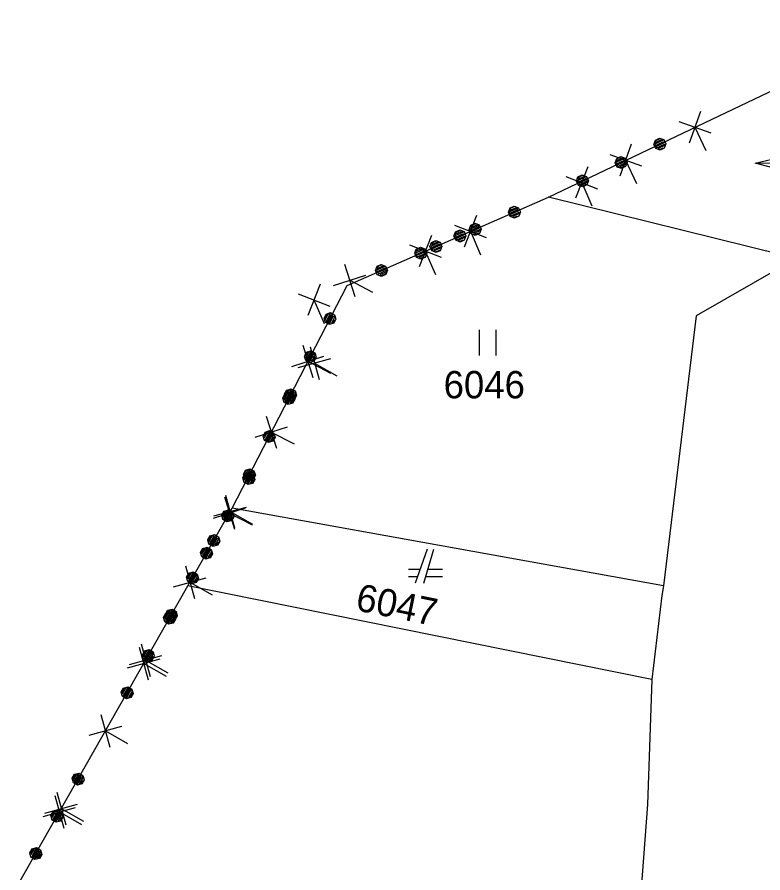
# Model space of a CAD drawing. Extents: x -266179 to -264727, y -1243225 to -1241702.
# Drawn here: x -265694.6 to -265650.9, y -1241809 to -1241758.9 of the extents above; entities that cross this region are included whole.
import ezdxf

# ---------------------------------------------------------------- set-up
doc = ezdxf.new("R2010")
doc.units = 0
for name, color, linetype in [('Vrstva 1', 7, 'Continuous'), ('Vrstva 19', 7, 'Continuous'), ('Vrstva 21', 7, 'Continuous')]:
    doc.layers.add(name, color=color, linetype=linetype)

msp = doc.modelspace()

# ---------------------------------------------------------------- linework, layer by layer
at = {"layer": 'Vrstva 1'}
for p, q in [((-265663.46, -1241769.44), (-265641.35, -1241758.91)), ((-265645.37, -1241767.516), (-265651.37, -1241767.464)), ((-265675.26, -1241774.61), (-265663.46, -1241769.44)), ((-265648.97, -1241773.03), (-265663.46, -1241769.44)), ((-265648.97, -1241773.03), (-265654.81, -1241776.39)), ((-265681.99, -1241787.64), (-265675.26, -1241774.61)), ((-265654.81, -1241776.39), (-265656.72, -1241792.19)), ((-265667.52, -1241777.21), (-265667.52, -1241778.71)), ((-265666.52, -1241778.71), (-265666.52, -1241777.21)), ((-265684.58, -1241792.19), (-265681.99, -1241787.64)), ((-265656.72, -1241792.19), (-265681.99, -1241787.64)), ((-265670.57, -1241790.04), (-265671.27, -1241792.04)), ((-265670.77, -1241792.04), (-265670.17, -1241790.04)), ((-265670.99, -1241791.24), (-265671.67, -1241791.24)), ((-265671.67, -1241791.64), (-265671.13, -1241791.64)), ((-265670.65, -1241791.64), (-265669.67, -1241791.64)), ((-265669.67, -1241791.24), (-265670.53, -1241791.24)), ((-265694.58, -1241809.77), (-265684.58, -1241792.19)), ((-265657.41, -1241797.68), (-265684.58, -1241792.19)), ((-265656.72, -1241792.19), (-265656.83, -1241792.75)), ((-265656.83, -1241792.75), (-265657.41, -1241797.68)), ((-265657.41, -1241797.68), (-265657.66, -1241804.99)), ((-265657.66, -1241804.99), (-265659.54, -1241829.41))]:
    msp.add_line(p, q, dxfattribs=at)
msp.add_lwpolyline([(-265649.374, -1241767.981), (-265651.37, -1241767.464), (-265649.366, -1241766.981)], dxfattribs=at)
at = {"layer": 'Vrstva 19'}
for p, q in [((-265663.46, -1241769.44), (-265641.35, -1241758.91)), ((-265675.26, -1241774.61), (-265663.46, -1241769.44)), ((-265681.99, -1241787.64), (-265675.26, -1241774.61)), ((-265684.58, -1241792.19), (-265681.99, -1241787.64)), ((-265694.58, -1241809.77), (-265684.58, -1241792.19))]:
    msp.add_line(p, q, dxfattribs=at)
for points in [[(-265656.961, -1241765.992), (-265656.708, -1241766.082), (-265656.592, -1241766.326), (-265656.682, -1241766.579), (-265656.926, -1241766.695), (-265657.179, -1241766.605), (-265657.295, -1241766.361), (-265657.205, -1241766.108), (-265656.961, -1241765.992), (-265656.98, -1241766.045), (-265657.197, -1241766.148), (-265657.217, -1241766.246), (-265656.873, -1241766.083), (-265656.767, -1241766.121), (-265657.236, -1241766.344), (-265657.202, -1241766.416), (-265656.732, -1241766.193), (-265656.698, -1241766.265), (-265657.168, -1241766.489), (-265657.142, -1241766.565), (-265656.673, -1241766.342), (-265656.674, -1241766.431), (-265657.045, -1241766.607), (-265656.965, -1241766.658), (-265656.748, -1241766.555)], [(-265659.228, -1241767.07), (-265658.975, -1241767.16), (-265658.859, -1241767.404), (-265658.948, -1241767.657), (-265659.192, -1241767.773), (-265659.445, -1241767.683), (-265659.561, -1241767.439), (-265659.472, -1241767.186), (-265659.228, -1241767.07), (-265659.22, -1241767.11), (-265659.436, -1241767.213), (-265659.474, -1241767.32), (-265659.113, -1241767.148), (-265659.006, -1241767.186), (-265659.512, -1241767.427), (-265659.478, -1241767.499), (-265658.972, -1241767.258), (-265658.938, -1241767.331), (-265659.443, -1241767.571), (-265659.409, -1241767.643), (-265658.903, -1241767.403), (-265658.941, -1241767.509), (-265659.302, -1241767.681), (-265659.196, -1241767.719), (-265658.979, -1241767.616)], [(-265661.494, -1241768.148), (-265661.241, -1241768.238), (-265661.125, -1241768.482), (-265661.215, -1241768.735), (-265661.459, -1241768.851), (-265661.712, -1241768.761), (-265661.828, -1241768.517), (-265661.738, -1241768.264), (-265661.494, -1241768.148), (-265661.468, -1241768.18), (-265661.685, -1241768.283), (-265661.723, -1241768.39), (-265661.362, -1241768.218), (-265661.273, -1241768.264), (-265661.761, -1241768.496), (-265661.726, -1241768.569), (-265661.248, -1241768.341), (-265661.204, -1241768.409), (-265661.683, -1241768.636), (-265661.648, -1241768.709), (-265661.17, -1241768.481), (-265661.181, -1241768.575), (-265661.569, -1241768.759), (-265661.471, -1241768.802), (-265661.219, -1241768.681)], [(-265665.466, -1241769.969), (-265665.216, -1241770.067), (-265665.108, -1241770.315), (-265665.205, -1241770.565), (-265665.453, -1241770.673), (-265665.703, -1241770.575), (-265665.811, -1241770.328), (-265665.713, -1241770.078), (-265665.466, -1241769.969), (-265665.487, -1241770.022), (-265665.707, -1241770.118), (-265665.729, -1241770.216), (-265665.381, -1241770.063), (-265665.276, -1241770.104), (-265665.752, -1241770.313), (-265665.72, -1241770.386), (-265665.244, -1241770.178), (-265665.212, -1241770.251), (-265665.688, -1241770.46), (-265665.665, -1241770.537), (-265665.189, -1241770.328), (-265665.193, -1241770.418), (-265665.569, -1241770.582), (-265665.491, -1241770.635), (-265665.271, -1241770.539)], [(-265667.765, -1241770.977), (-265667.515, -1241771.075), (-265667.406, -1241771.322), (-265667.504, -1241771.572), (-265667.752, -1241771.681), (-265668.002, -1241771.583), (-265668.11, -1241771.336), (-265668.012, -1241771.085), (-265667.765, -1241770.977), (-265667.758, -1241771.018), (-265667.978, -1241771.114), (-265668.019, -1241771.219), (-265667.653, -1241771.059), (-265667.547, -1241771.1), (-265668.06, -1241771.325), (-265668.028, -1241771.398), (-265667.515, -1241771.173), (-265667.483, -1241771.246), (-265667.996, -1241771.471), (-265667.964, -1241771.544), (-265667.451, -1241771.32), (-265667.492, -1241771.425), (-265667.859, -1241771.586), (-265667.753, -1241771.627), (-265667.533, -1241771.53)], [(-265668.656, -1241771.367), (-265668.406, -1241771.465), (-265668.298, -1241771.712), (-265668.395, -1241771.963), (-265668.643, -1241772.071), (-265668.893, -1241771.973), (-265669.001, -1241771.726), (-265668.904, -1241771.476), (-265668.656, -1241771.367), (-265668.677, -1241771.42), (-265668.897, -1241771.516), (-265668.92, -1241771.614), (-265668.572, -1241771.461), (-265668.466, -1241771.502), (-265668.942, -1241771.711), (-265668.91, -1241771.784), (-265668.434, -1241771.575), (-265668.402, -1241771.649), (-265668.878, -1241771.857), (-265668.855, -1241771.935), (-265668.379, -1241771.726), (-265668.383, -1241771.815), (-265668.759, -1241771.98), (-265668.681, -1241772.033), (-265668.461, -1241771.937)], [(-265670.064, -1241771.984), (-265669.814, -1241772.082), (-265669.705, -1241772.329), (-265669.803, -1241772.58), (-265670.051, -1241772.688), (-265670.301, -1241772.59), (-265670.409, -1241772.343), (-265670.311, -1241772.093), (-265670.064, -1241771.984), (-265670.039, -1241772.017), (-265670.259, -1241772.113), (-265670.3, -1241772.219), (-265669.934, -1241772.058), (-265669.846, -1241772.107), (-265670.341, -1241772.324), (-265670.309, -1241772.397), (-265669.823, -1241772.185), (-265669.782, -1241772.254), (-265670.268, -1241772.467), (-265670.236, -1241772.54), (-265669.75, -1241772.327), (-265669.764, -1241772.42), (-265670.158, -1241772.593), (-265670.061, -1241772.638), (-265669.805, -1241772.526)], [(-265670.955, -1241772.375), (-265670.705, -1241772.472), (-265670.597, -1241772.72), (-265670.694, -1241772.97), (-265670.942, -1241773.078), (-265671.192, -1241772.981), (-265671.3, -1241772.733), (-265671.203, -1241772.483), (-265670.955, -1241772.375), (-265670.948, -1241772.415), (-265671.168, -1241772.512), (-265671.209, -1241772.617), (-265670.843, -1241772.456), (-265670.738, -1241772.498), (-265671.251, -1241772.722), (-265671.218, -1241772.796), (-265670.706, -1241772.571), (-265670.673, -1241772.644), (-265671.186, -1241772.869), (-265671.154, -1241772.942), (-265670.641, -1241772.717), (-265670.682, -1241772.823), (-265671.049, -1241772.983), (-265670.943, -1241773.024), (-265670.724, -1241772.928)], [(-265673.254, -1241773.382), (-265673.004, -1241773.48), (-265672.896, -1241773.727), (-265672.993, -1241773.977), (-265673.241, -1241774.086), (-265673.491, -1241773.988), (-265673.599, -1241773.741), (-265673.502, -1241773.49), (-265673.254, -1241773.382), (-265673.229, -1241773.415), (-265673.449, -1241773.511), (-265673.49, -1241773.616), (-265673.124, -1241773.456), (-265673.037, -1241773.505), (-265673.531, -1241773.722), (-265673.499, -1241773.795), (-265673.014, -1241773.582), (-265672.972, -1241773.652), (-265673.458, -1241773.864), (-265673.426, -1241773.938), (-265672.94, -1241773.725), (-265672.954, -1241773.818), (-265673.348, -1241773.991), (-265673.252, -1241774.036), (-265672.995, -1241773.924)], [(-265676.485, -1241776.285), (-265676.229, -1241776.203), (-265675.989, -1241776.327), (-265675.907, -1241776.583), (-265676.031, -1241776.823), (-265676.287, -1241776.904), (-265676.527, -1241776.78), (-265676.609, -1241776.524), (-265676.485, -1241776.285), (-265676.468, -1241776.338), (-265676.578, -1241776.552), (-265676.534, -1241776.642), (-265676.36, -1241776.304), (-265676.252, -1241776.27), (-265676.491, -1241776.732), (-265676.42, -1241776.768), (-265676.181, -1241776.306), (-265676.11, -1241776.343), (-265676.349, -1241776.805), (-265676.282, -1241776.851), (-265676.044, -1241776.389), (-265675.991, -1241776.461), (-265676.179, -1241776.825), (-265676.085, -1241776.818), (-265675.975, -1241776.604)], [(-265677.637, -1241778.515), (-265677.381, -1241778.433), (-265677.141, -1241778.557), (-265677.059, -1241778.813), (-265677.183, -1241779.053), (-265677.439, -1241779.134), (-265677.679, -1241779.011), (-265677.761, -1241778.755), (-265677.637, -1241778.515), (-265677.606, -1241778.542), (-265677.716, -1241778.755), (-265677.682, -1241778.863), (-265677.498, -1241778.508), (-265677.39, -1241778.473), (-265677.647, -1241778.971), (-265677.576, -1241779.007), (-265677.319, -1241778.51), (-265677.248, -1241778.547), (-265677.505, -1241779.044), (-265677.434, -1241779.081), (-265677.177, -1241778.583), (-265677.143, -1241778.691), (-265677.326, -1241779.046), (-265677.219, -1241779.012), (-265677.108, -1241778.799)], [(-265678.789, -1241780.745), (-265678.533, -1241780.663), (-265678.293, -1241780.787), (-265678.211, -1241781.043), (-265678.335, -1241781.283), (-265678.591, -1241781.365), (-265678.831, -1241781.241), (-265678.913, -1241780.985), (-265678.789, -1241780.745), (-265678.749, -1241780.754), (-265678.859, -1241780.967), (-265678.824, -1241781.075), (-265678.641, -1241780.72), (-265678.542, -1241780.703), (-265678.79, -1241781.183), (-265678.719, -1241781.22), (-265678.476, -1241780.749), (-265678.4, -1241780.777), (-265678.643, -1241781.248), (-265678.572, -1241781.284), (-265678.329, -1241780.813), (-265678.281, -1241780.894), (-265678.478, -1241781.277), (-265678.375, -1241781.251), (-265678.247, -1241781.002)], [(-265678.901, -1241780.963), (-265678.645, -1241780.881), (-265678.405, -1241781.005), (-265678.324, -1241781.261), (-265678.448, -1241781.501), (-265678.704, -1241781.583), (-265678.944, -1241781.459), (-265679.025, -1241781.203), (-265678.901, -1241780.963), (-265678.884, -1241781.017), (-265678.994, -1241781.23), (-265678.951, -1241781.32), (-265678.776, -1241780.982), (-265678.669, -1241780.948), (-265678.907, -1241781.41), (-265678.836, -1241781.447), (-265678.597, -1241780.985), (-265678.526, -1241781.021), (-265678.765, -1241781.483), (-265678.699, -1241781.529), (-265678.46, -1241781.067), (-265678.407, -1241781.139), (-265678.595, -1241781.504), (-265678.501, -1241781.496), (-265678.391, -1241781.283)], [(-265680.053, -1241783.193), (-265679.797, -1241783.111), (-265679.557, -1241783.235), (-265679.476, -1241783.491), (-265679.6, -1241783.731), (-265679.856, -1241783.813), (-265680.096, -1241783.689), (-265680.177, -1241783.433), (-265680.053, -1241783.193), (-265680.022, -1241783.22), (-265680.132, -1241783.433), (-265680.098, -1241783.541), (-265679.914, -1241783.186), (-265679.807, -1241783.151), (-265680.064, -1241783.649), (-265679.993, -1241783.686), (-265679.736, -1241783.188), (-265679.665, -1241783.225), (-265679.922, -1241783.722), (-265679.85, -1241783.759), (-265679.593, -1241783.262), (-265679.559, -1241783.369), (-265679.743, -1241783.725), (-265679.635, -1241783.69), (-265679.525, -1241783.477)], [(-265681.221, -1241785.644), (-265680.962, -1241785.573), (-265680.728, -1241785.707), (-265680.657, -1241785.966), (-265680.79, -1241786.201), (-265681.049, -1241786.272), (-265681.284, -1241786.138), (-265681.355, -1241785.879), (-265681.221, -1241785.644), (-265681.206, -1241785.699), (-265681.325, -1241785.907), (-265681.285, -1241785.999), (-265681.097, -1241785.669), (-265680.988, -1241785.639), (-265681.246, -1241786.091), (-265681.176, -1241786.131), (-265680.919, -1241785.679), (-265680.849, -1241785.718), (-265681.106, -1241786.17), (-265681.042, -1241786.218), (-265680.785, -1241785.767), (-265680.735, -1241785.841), (-265680.938, -1241786.197), (-265680.844, -1241786.193), (-265680.725, -1241785.985)], [(-265681.205, -1241785.423), (-265680.949, -1241785.341), (-265680.709, -1241785.465), (-265680.628, -1241785.721), (-265680.752, -1241785.961), (-265681.008, -1241786.043), (-265681.247, -1241785.919), (-265681.329, -1241785.663), (-265681.205, -1241785.423), (-265681.165, -1241785.432), (-265681.275, -1241785.646), (-265681.241, -1241785.753), (-265681.057, -1241785.398), (-265680.959, -1241785.381), (-265681.206, -1241785.861), (-265681.135, -1241785.898), (-265680.892, -1241785.427), (-265680.816, -1241785.455), (-265681.06, -1241785.926), (-265680.989, -1241785.962), (-265680.745, -1241785.492), (-265680.697, -1241785.573), (-265680.895, -1241785.955), (-265680.791, -1241785.929), (-265680.663, -1241785.681)], [(-265682.464, -1241787.825), (-265682.205, -1241787.754), (-265681.97, -1241787.888), (-265681.899, -1241788.147), (-265682.033, -1241788.382), (-265682.292, -1241788.453), (-265682.526, -1241788.319), (-265682.597, -1241788.06), (-265682.464, -1241787.825), (-265682.434, -1241787.854), (-265682.553, -1241788.062), (-265682.523, -1241788.171), (-265682.325, -1241787.824), (-265682.216, -1241787.794), (-265682.493, -1241788.281), (-265682.423, -1241788.32), (-265682.146, -1241787.834), (-265682.077, -1241787.873), (-265682.354, -1241788.36), (-265682.284, -1241788.399), (-265682.007, -1241787.913), (-265681.977, -1241788.022), (-265682.175, -1241788.369), (-265682.066, -1241788.34), (-265681.947, -1241788.131)], [(-265683.281, -1241789.264), (-265683.022, -1241789.193), (-265682.788, -1241789.326), (-265682.717, -1241789.585), (-265682.85, -1241789.82), (-265683.109, -1241789.891), (-265683.344, -1241789.757), (-265683.415, -1241789.498), (-265683.281, -1241789.264), (-265683.267, -1241789.318), (-265683.385, -1241789.527), (-265683.345, -1241789.618), (-265683.157, -1241789.288), (-265683.048, -1241789.258), (-265683.306, -1241789.71), (-265683.236, -1241789.75), (-265682.979, -1241789.298), (-265682.909, -1241789.338), (-265683.167, -1241789.789), (-265683.102, -1241789.838), (-265682.845, -1241789.386), (-265682.795, -1241789.46), (-265682.998, -1241789.816), (-265682.904, -1241789.813), (-265682.785, -1241789.604)], [(-265683.706, -1241790.006), (-265683.447, -1241789.935), (-265683.212, -1241790.069), (-265683.141, -1241790.328), (-265683.275, -1241790.563), (-265683.534, -1241790.634), (-265683.769, -1241790.5), (-265683.84, -1241790.241), (-265683.706, -1241790.006), (-265683.666, -1241790.017), (-265683.785, -1241790.226), (-265683.755, -1241790.335), (-265683.557, -1241789.988), (-265683.458, -1241789.975), (-265683.725, -1241790.444), (-265683.656, -1241790.484), (-265683.393, -1241790.023), (-265683.319, -1241790.054), (-265683.581, -1241790.515), (-265683.512, -1241790.554), (-265683.249, -1241790.094), (-265683.205, -1241790.177), (-265683.418, -1241790.55), (-265683.313, -1241790.529), (-265683.175, -1241790.286)], [(-265684.524, -1241791.445), (-265684.265, -1241791.374), (-265684.03, -1241791.507), (-265683.959, -1241791.766), (-265684.093, -1241792.001), (-265684.352, -1241792.072), (-265684.586, -1241791.938), (-265684.657, -1241791.679), (-265684.524, -1241791.445), (-265684.494, -1241791.473), (-265684.613, -1241791.682), (-265684.583, -1241791.791), (-265684.385, -1241791.443), (-265684.276, -1241791.413), (-265684.553, -1241791.9), (-265684.483, -1241791.939), (-265684.206, -1241791.453), (-265684.137, -1241791.492), (-265684.414, -1241791.979), (-265684.344, -1241792.019), (-265684.067, -1241791.532), (-265684.037, -1241791.641), (-265684.235, -1241791.989), (-265684.126, -1241791.959), (-265684.007, -1241791.75)], [(-265685.766, -1241793.626), (-265685.507, -1241793.554), (-265685.272, -1241793.688), (-265685.201, -1241793.947), (-265685.335, -1241794.182), (-265685.594, -1241794.253), (-265685.829, -1241794.119), (-265685.9, -1241793.86), (-265685.766, -1241793.626), (-265685.726, -1241793.637), (-265685.845, -1241793.845), (-265685.815, -1241793.954), (-265685.617, -1241793.607), (-265685.518, -1241793.594), (-265685.785, -1241794.063), (-265685.716, -1241794.103), (-265685.454, -1241793.642), (-265685.379, -1241793.673), (-265685.641, -1241794.134), (-265685.572, -1241794.174), (-265685.31, -1241793.713), (-265685.265, -1241793.796), (-265685.478, -1241794.17), (-265685.374, -1241794.148), (-265685.235, -1241793.905)], [(-265685.873, -1241793.813), (-265685.614, -1241793.742), (-265685.379, -1241793.875), (-265685.308, -1241794.134), (-265685.441, -1241794.369), (-265685.7, -1241794.44), (-265685.935, -1241794.307), (-265686.006, -1241794.048), (-265685.873, -1241793.813), (-265685.858, -1241793.868), (-265685.976, -1241794.076), (-265685.936, -1241794.168), (-265685.749, -1241793.838), (-265685.64, -1241793.808), (-265685.896, -1241794.26), (-265685.827, -1241794.299), (-265685.57, -1241793.847), (-265685.5, -1241793.887), (-265685.757, -1241794.339), (-265685.693, -1241794.387), (-265685.436, -1241793.935), (-265685.386, -1241794.009), (-265685.589, -1241794.366), (-265685.494, -1241794.362), (-265685.376, -1241794.153)], [(-265687.113, -1241795.995), (-265686.854, -1241795.924), (-265686.619, -1241796.058), (-265686.548, -1241796.317), (-265686.681, -1241796.551), (-265686.94, -1241796.623), (-265687.175, -1241796.489), (-265687.246, -1241796.23), (-265687.113, -1241795.995), (-265687.083, -1241796.024), (-265687.202, -1241796.233), (-265687.172, -1241796.342), (-265686.974, -1241795.994), (-265686.865, -1241795.964), (-265687.142, -1241796.451), (-265687.072, -1241796.49), (-265686.795, -1241796.003), (-265686.726, -1241796.043), (-265687.002, -1241796.53), (-265686.933, -1241796.569), (-265686.656, -1241796.082), (-265686.626, -1241796.192), (-265686.824, -1241796.539), (-265686.715, -1241796.509), (-265686.596, -1241796.301)], [(-265688.353, -1241798.178), (-265688.094, -1241798.106), (-265687.859, -1241798.24), (-265687.788, -1241798.499), (-265687.921, -1241798.734), (-265688.18, -1241798.805), (-265688.415, -1241798.671), (-265688.486, -1241798.412), (-265688.353, -1241798.178), (-265688.313, -1241798.189), (-265688.432, -1241798.397), (-265688.402, -1241798.507), (-265688.204, -1241798.159), (-265688.105, -1241798.146), (-265688.372, -1241798.616), (-265688.302, -1241798.655), (-265688.04, -1241798.194), (-265687.966, -1241798.225), (-265688.228, -1241798.686), (-265688.158, -1241798.725), (-265687.896, -1241798.265), (-265687.852, -1241798.348), (-265688.064, -1241798.722), (-265687.96, -1241798.7), (-265687.822, -1241798.457)], [(-265691.225, -1241803.223), (-265690.966, -1241803.151), (-265690.731, -1241803.285), (-265690.66, -1241803.544), (-265690.793, -1241803.779), (-265691.052, -1241803.85), (-265691.287, -1241803.716), (-265691.358, -1241803.457), (-265691.225, -1241803.223), (-265691.21, -1241803.277), (-265691.329, -1241803.486), (-265691.289, -1241803.578), (-265691.101, -1241803.247), (-265690.992, -1241803.217), (-265691.249, -1241803.669), (-265691.179, -1241803.709), (-265690.922, -1241803.257), (-265690.853, -1241803.296), (-265691.11, -1241803.748), (-265691.045, -1241803.797), (-265690.788, -1241803.344), (-265690.738, -1241803.419), (-265690.941, -1241803.775), (-265690.847, -1241803.771), (-265690.728, -1241803.563)], [(-265692.465, -1241805.405), (-265692.206, -1241805.334), (-265691.971, -1241805.467), (-265691.9, -1241805.726), (-265692.033, -1241805.961), (-265692.293, -1241806.032), (-265692.527, -1241805.899), (-265692.599, -1241805.64), (-265692.465, -1241805.405), (-265692.435, -1241805.433), (-265692.554, -1241805.642), (-265692.524, -1241805.751), (-265692.326, -1241805.403), (-265692.217, -1241805.373), (-265692.494, -1241805.86), (-265692.424, -1241805.9), (-265692.148, -1241805.413), (-265692.078, -1241805.452), (-265692.355, -1241805.939), (-265692.285, -1241805.979), (-265692.009, -1241805.492), (-265691.979, -1241805.601), (-265692.176, -1241805.949), (-265692.067, -1241805.919), (-265691.948, -1241805.71)], [(-265693.705, -1241807.587), (-265693.446, -1241807.516), (-265693.212, -1241807.649), (-265693.14, -1241807.908), (-265693.274, -1241808.143), (-265693.533, -1241808.214), (-265693.767, -1241808.081), (-265693.839, -1241807.822), (-265693.705, -1241807.587), (-265693.666, -1241807.598), (-265693.784, -1241807.807), (-265693.754, -1241807.916), (-265693.557, -1241807.568), (-265693.457, -1241807.555), (-265693.724, -1241808.025), (-265693.655, -1241808.064), (-265693.393, -1241807.604), (-265693.318, -1241807.635), (-265693.58, -1241808.095), (-265693.511, -1241808.135), (-265693.249, -1241807.674), (-265693.204, -1241807.757), (-265693.416, -1241808.131), (-265693.312, -1241808.11), (-265693.174, -1241807.866)]]:
    msp.add_lwpolyline(points, dxfattribs=at)
at = {"layer": 'Vrstva 21'}
for p, q in [((-265663.46, -1241769.44), (-265641.35, -1241758.91)), ((-265654.562, -1241764.425), (-265655.225, -1241766.29)), ((-265655.826, -1241765.026), (-265653.961, -1241765.689)), ((-265654.894, -1241765.358), (-265654.249, -1241766.712)), ((-265658.615, -1241766.355), (-265659.278, -1241768.221)), ((-265659.88, -1241766.957), (-265658.014, -1241767.619)), ((-265658.947, -1241767.288), (-265658.302, -1241768.643)), ((-265661.161, -1241767.668), (-265661.881, -1241769.512)), ((-265662.443, -1241768.23), (-265660.599, -1241768.95)), ((-265661.521, -1241768.59), (-265660.919, -1241769.964)), ((-265675.26, -1241774.61), (-265663.46, -1241769.44)), ((-265667.68, -1241770.524), (-265668.4, -1241772.368)), ((-265668.962, -1241771.086), (-265667.118, -1241771.806)), ((-265668.04, -1241771.446), (-265667.438, -1241772.82)), ((-265670.32, -1241771.682), (-265671.04, -1241773.526)), ((-265671.602, -1241772.244), (-265669.758, -1241772.964)), ((-265670.68, -1241772.604), (-265670.078, -1241773.978)), ((-265675.407, -1241773.37), (-265674.806, -1241775.256)), ((-265676.049, -1241774.613), (-265674.163, -1241774.012)), ((-265681.99, -1241787.64), (-265675.26, -1241774.61)), ((-265676.839, -1241774.538), (-265677.559, -1241776.382)), ((-265675.106, -1241774.313), (-265673.774, -1241775.001)), ((-265678.121, -1241775.1), (-265676.277, -1241775.82)), ((-265677.199, -1241775.46), (-265676.597, -1241776.834)), ((-265677.855, -1241778.109), (-265677.254, -1241779.996)), ((-265677.42, -1241778.2), (-265676.896, -1241780.11)), ((-265678.498, -1241779.353), (-265676.611, -1241778.752)), ((-265678.113, -1241779.417), (-265676.203, -1241778.893)), ((-265677.554, -1241779.053), (-265676.222, -1241779.741)), ((-265677.158, -1241779.155), (-265675.855, -1241779.897)), ((-265679.996, -1241782.254), (-265679.395, -1241784.141)), ((-265680.639, -1241783.498), (-265678.752, -1241782.897)), ((-265679.696, -1241783.197), (-265678.363, -1241783.886)), ((-265682.444, -1241786.994), (-265681.843, -1241788.88)), ((-265682.37, -1241786.889), (-265681.846, -1241788.799)), ((-265684.58, -1241792.19), (-265681.99, -1241787.64)), ((-265683.087, -1241788.238), (-265681.201, -1241787.637)), ((-265683.063, -1241788.106), (-265681.153, -1241787.582)), ((-265682.144, -1241787.937), (-265680.811, -1241788.626)), ((-265682.108, -1241787.844), (-265680.804, -1241788.586)), ((-265684.724, -1241791.031), (-265684.2, -1241792.941)), ((-265694.58, -1241809.77), (-265684.58, -1241792.19)), ((-265685.417, -1241792.248), (-265683.507, -1241791.724)), ((-265684.462, -1241791.986), (-265683.159, -1241792.729)), ((-265687.317, -1241795.581), (-265686.791, -1241797.49)), ((-265687.428, -1241795.776), (-265686.902, -1241797.685)), ((-265688.12, -1241796.994), (-265686.211, -1241796.468)), ((-265688.008, -1241796.798), (-265686.099, -1241796.272)), ((-265687.054, -1241796.535), (-265685.75, -1241797.276)), ((-265687.165, -1241796.731), (-265685.861, -1241797.472)), ((-265689.674, -1241799.72), (-265689.15, -1241801.63)), ((-265690.367, -1241800.937), (-265688.457, -1241800.413)), ((-265689.412, -1241800.675), (-265688.108, -1241801.418)), ((-265692.369, -1241804.47), (-265691.843, -1241806.379)), ((-265692.258, -1241804.275), (-265691.732, -1241806.184)), ((-265693.061, -1241805.688), (-265691.152, -1241805.162)), ((-265692.949, -1241805.492), (-265691.04, -1241804.966)), ((-265692.106, -1241805.425), (-265690.802, -1241806.166)), ((-265691.995, -1241805.229), (-265690.691, -1241805.97))]:
    msp.add_line(p, q, dxfattribs=at)

# ---------------------------------------------------------------- texts
at = {"layer": 'Vrstva 1'}
msp.add_text('6046', height=1.6, dxfattribs=at).set_placement((-265669.605, -1241781.22))
msp.add_text('6047', height=1.6, rotation=348.5875, dxfattribs=at).set_placement((-265674.824, -1241793.61))

doc.saveas('drawing.dxf')
